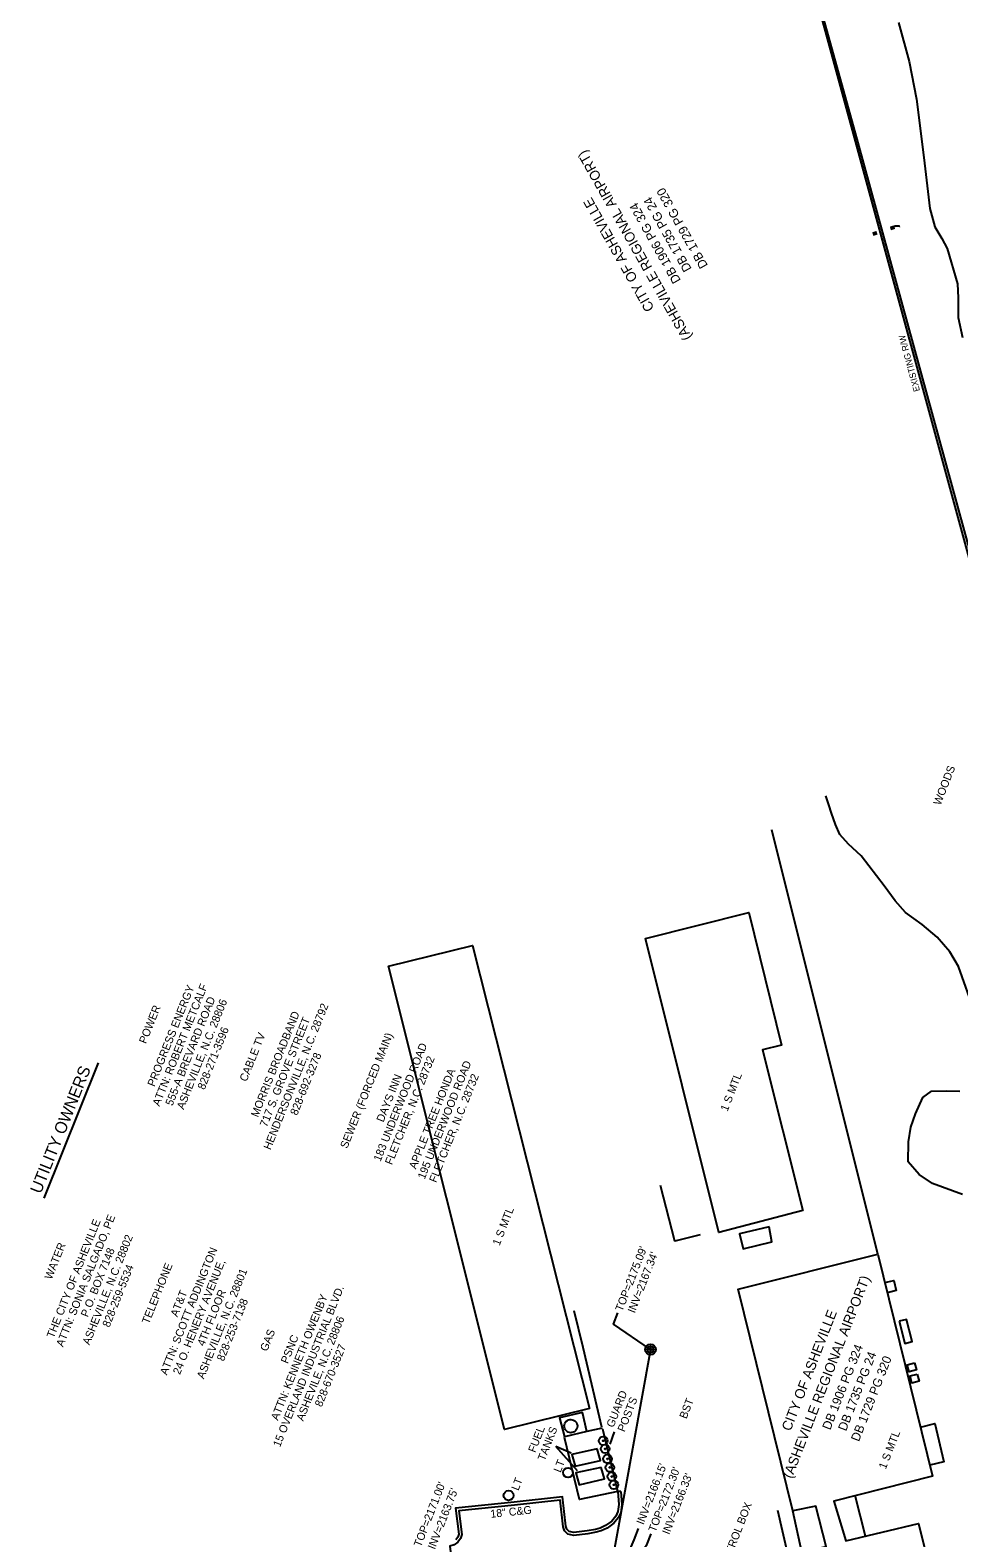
# Model space of a CAD drawing. Extents: x 945964 to 948456, y 631061 to 636061.
# Drawn here: x 946196 to 946664, y 633631 to 634391 of the extents above; entities that cross this region are included whole.
import ezdxf

# ---------------------------------------------------------------- set-up
doc = ezdxf.new("R2010")
doc.units = 0
for name, color, linetype in [('Exist Building', 7, 'Continuous'), ('Exist Building Text', 7, 'Continuous'), ('Exist Horizontal Alignment', 7, 'Continuous'), ('Exist Other Culture AG Tank', 7, 'Continuous'), ('Exist Other Culture AG Tank Leader', 7, 'Continuous'), ('Exist Other Culture AG Tank Text', 7, 'Continuous'), ('Exist Other Culture Fence Line', 7, 'Continuous'), ('Exist Other Culture Located Object CELL', 7, 'Continuous'), ('Exist Other Culture Located Object Leader', 7, 'Continuous'), ('Exist Other Culture Located Object Text', 7, 'Continuous'), ('Exist Property Deed Book Text', 7, 'Continuous'), ('Exist Property Owner Text', 7, 'Continuous'), ('Exist Right of Way Control of Access CA Symbol CELL', 7, 'Continuous'), ('Exist Right of Way Line', 7, 'Continuous'), ('Exist Right of Way Line Text', 7, 'Continuous'), ('Exist Roads Curbs', 7, 'Continuous'), ('Exist Roads Curbs Text', 7, 'Continuous'), ('Exist Roads EOP', 7, 'Continuous'), ('Exist Roads EOP Other', 7, 'Continuous'), ('Exist Roads EOP Other Text', 7, 'Continuous'), ('Exist Structure Minor Catch Basin Top Elevation', 7, 'Continuous'), ('Exist Structure Minor Pipes HDPE 15 Inch Invert', 7, 'Continuous'), ('Exist Structure Minor Pipes HDPE 18 Inch Invert', 7, 'Continuous'), ('Exist Utilities Gas UG Line Text', 7, 'Continuous'), ('Exist Utilities Other Pole CELL', 7, 'Continuous'), ('Exist Utilities Other Pole Text', 7, 'Continuous'), ('Exist Utilities Power UG Cable Text', 7, 'Continuous'), ('Exist Utilities Sanitary Sewer Manhole CELL', 7, 'Continuous'), ('Exist Utilities Sanitary Sewer Manhole Top Elevation', 7, 'Continuous'), ('Exist Utilities Sanitary Sewer UG Line', 7, 'Continuous'), ('Exist Utilities Sanitary Sewer UG Line Invert Elevation', 7, 'Continuous'), ('Exist Utilities Sanitary Sewer UG Line Text', 7, 'Continuous'), ('Exist Utilities Telephone UG Cable Text', 7, 'Continuous'), ('Exist Utilities TV UG Cable Text', 7, 'Continuous'), ('Exist Utilities Water UG Line', 7, 'Continuous'), ('Exist Utilities Water UG Line Text', 7, 'Continuous'), ('Exist Vegetation Woods Line', 7, 'Continuous'), ('Exist Vegetation Woods Line Text', 7, 'Continuous')]:
    doc.layers.add(name, color=color, linetype=linetype)

# ---------------------------------------------------------------- blocks, each defined once
blk = doc.blocks.new('EXIST UTILITIES SANITARY SEWER MANHOLE')
at = {"layer": 'Exist Utilities Sanitary Sewer Manhole CELL'}
blk.add_lwpolyline([(0, 0.034), (0, -0.034), (0, 0), (0.034, 0), (-0.034, 0)], dxfattribs=at)
for radius in [0.0539, 0.0342]:
    blk.add_circle((0, 0), radius, dxfattribs=at)
blk = doc.blocks.new('EXIST UTILITIES OTHER POLE')
at = {"layer": 'Exist Utilities Other Pole CELL'}
blk.add_circle((0, 0), 0.0493, dxfattribs=at)
blk = doc.blocks.new('EXIST OTHER CULTURE LOCATED OBJECT')
at = {"layer": 'Exist Other Culture Located Object CELL'}
for radius in [0.0436, 0.0048]:
    blk.add_circle((0, 0), radius, dxfattribs=at)

msp = doc.modelspace()

# ---------------------------------------------------------------- linework, layer by layer
at = {"layer": 'Exist Building'}
for points in [[(946585.51, 633796), (946543.09, 633784.88), (946506.06, 633933.07), (946558.17, 633946.19), (946574.77, 633879.35), (946565.18, 633877.05)], [(946477.89, 633696.25), (946435.09, 633685.56), (946376.62, 633919.21), (946418.84, 633929.55)], [(946568.47, 633787.79), (946553.56, 633784.29), (946555.39, 633776.67), (946569.81, 633780.2)], [(946623.36, 633773.95), (946650.9, 633662.1), (946601.09, 633649.58), (946607.19, 633629.53), (946643.78, 633638.28), (946658.46, 633579.54), (946600.11, 633564.89), (946592.6, 633586.8), (946584.76, 633584.87), (946581, 633599.34), (946588.81, 633601.19), (946585.03, 633623.78), (946597.19, 633626.71), (946592.09, 633646.95), (946580.49, 633644.56), (946552.84, 633756.37)]]:
    msp.add_lwpolyline(points, close=True, dxfattribs=at)
for points in [[(946476.56, 633684.58), (946474.3, 633694.22), (946462.85, 633691.49), (946465.22, 633681.98)], [(946484.35, 633686.25), (946476.56, 633684.58), (946465.22, 633681.98)]]:
    msp.add_lwpolyline(points, dxfattribs=at)
at = {"layer": 'Exist Horizontal Alignment'}
msp.add_arc((941215.95, 632723.7), 5729.58, 16.26287, 23.58343, dxfattribs=at)
at = {"layer": 'Exist Other Culture AG Tank'}
for points in [[(946481.69, 633675.79), (946469.02, 633673.09), (946470.62, 633667.11), (946483.37, 633670.02), (946481.78, 633675.83)], [(946483.73, 633666.48), (946471.07, 633663.78), (946472.67, 633657.8), (946485.42, 633660.71), (946483.83, 633666.52)]]:
    msp.add_lwpolyline(points, dxfattribs=at)
msp.add_ellipse((946468.49, 633687.32), major_axis=(3.04, -1.35), ratio=0.999999, dxfattribs=at)
at = {"layer": 'Exist Other Culture AG Tank Leader'}
for points in [[(946468.58, 633673.73), (946460.88, 633676.99)], [(946471.9, 633664.71), (946460.88, 633676.99)]]:
    msp.add_lwpolyline(points, dxfattribs=at)
at = {"layer": 'Exist Other Culture Fence Line'}
for points in [[(946878.27, 633607.67), (946888.64, 633643.47), (946880.77, 633649.9), (946866.85, 633668.33), (946820.19, 633740.22), (946774.6, 633810.54), (946747.06, 633866.82), (946715.89, 633963.4), (946695.94, 634031.44), (946673.26, 634115.84), (946613.35, 634334.02), (946562.75, 634516.44)], [(946623.36, 633773.95), (946569.82, 633987.91)]]:
    msp.add_lwpolyline(points, dxfattribs=at)
at = {"layer": 'Exist Other Culture Located Object Leader'}
msp.add_lwpolyline([(946488.38, 633678.18), (946490.47, 633684.46)], dxfattribs=at)
at = {"layer": 'Exist Right of Way Control of Access CA Symbol CELL'}
msp.add_line((946623.16, 634293.78), (946623.16, 634293.78), dxfattribs=at)
at = {"layer": 'Exist Right of Way Line'}
msp.add_lwpolyline([(946574.77, 634471.14), (946704.36, 633996.2)], dxfattribs=at)
at = {"layer": 'Exist Roads Curbs'}
for points in [[(946492.19, 633654.29), (946492.71, 633647.87), (946492.23, 633644.24), (946491.13, 633641.88), (946489.13, 633639.47), (946486.01, 633637.17), (946483.34, 633635.89), (946480.96, 633635.29), (946476.78, 633634.55), (946470.03, 633633.77), (946467.67, 633634.19), (946466.54, 633635.33), (946466.01, 633636.85), (946464.35, 633651.62), (946439.85, 633648.99), (946410.38, 633645.9), (946411.95, 633632.87), (946411.54, 633631.3), (946410.44, 633629.95)], [(946578.16, 633622.11), (946572.81, 633644.83)]]:
    msp.add_lwpolyline(points, dxfattribs=at)
at = {"layer": 'Exist Roads EOP'}
msp.add_lwpolyline([(946493.69, 633654.41), (946494.22, 633647.83), (946493.68, 633643.82), (946492.41, 633641.07), (946490.17, 633638.37), (946486.79, 633635.88), (946483.85, 633634.47), (946481.28, 633633.83), (946477, 633633.06), (946469.98, 633632.26), (946466.94, 633632.79), (946465.23, 633634.52), (946464.54, 633636.52), (946463.03, 633649.97), (946440.01, 633647.49), (946412.05, 633644.57), (946413.47, 633632.77), (946412.92, 633630.61), (946411.47, 633628.83), (946409.61, 633627.56), (946407.41, 633626.84), (946409.13, 633613.1)], dxfattribs=at)
at = {"layer": 'Exist Roads EOP Other'}
for points in [[(946533.63, 633783.73), (946520.93, 633780.46), (946513.67, 633808.64)], [(946626.85, 633759.77), (946631.43, 633760.78), (946632.57, 633755.64), (946628.13, 633754.55)], [(946484.16, 633686.71), (946474.64, 633726.97), (946470.13, 633745.43)], [(946493.69, 633654.41), (946492.69, 633654.33), (946492.19, 633654.29), (946484.57, 633685.73)], [(946644.81, 633686.81), (946652.11, 633688.58), (946656.56, 633669.32), (946649.52, 633667.71)], [(946492.19, 633654.29), (946472.83, 633650.29), (946465.3, 633681.56)], [(946617.11, 633631.9), (946611.8, 633652.27)], [(946585.03, 633623.78), (946580.49, 633644.56)]]:
    msp.add_lwpolyline(points, dxfattribs=at)
for points in [[(946634, 633740.18), (946636.88, 633729.01), (946640.56, 633729.96), (946637.67, 633741.13)], [(946641.77, 633719.22), (946642.78, 633715.63), (946639.15, 633714.6), (946638.13, 633718.2)], [(946643.18, 633713.58), (946644.11, 633709.98), (946640.48, 633709.03), (946639.54, 633712.63)]]:
    msp.add_lwpolyline(points, close=True, dxfattribs=at)
at = {"layer": 'Exist Structure Minor Catch Basin Top Elevation'}
msp.add_lwpolyline([(946493.66, 633612.2), (946506.75, 633627.44), (946508.94, 633633.03)], dxfattribs=at)
at = {"layer": 'Exist Structure Minor Pipes HDPE 18 Inch Invert'}
msp.add_lwpolyline([(946492.54, 633611.54), (946500.47, 633630.05), (946502.66, 633635.64)], dxfattribs=at)
at = {"layer": 'Exist Utilities Sanitary Sewer Manhole Top Elevation'}
msp.add_lwpolyline([(946508.67, 633725.95), (946490.07, 633738.77), (946492.26, 633744.36)], dxfattribs=at)
at = {"layer": 'Exist Utilities Sanitary Sewer UG Line'}
msp.add_lwpolyline([(946508.67, 633725.95), (946453.33, 633420.85)], dxfattribs=at)
at = {"layer": 'Exist Utilities Water UG Line'}
msp.add_lwpolyline([(946202.9, 633802.22), (946230.27, 633870.48)], dxfattribs=at)
at = {"layer": 'Exist Vegetation Woods Line'}
for points in [[(946633.79, 634394.82), (946639.02, 634375.12), (946642.78, 634356.07), (946646.5, 634326.78), (946649.44, 634301.05), (946652.06, 634291.81), (946655.53, 634285.87), (946658.26, 634280.77), (946663.5, 634263.07), (946663.77, 634255.98), (946663.76, 634246.02), (946665.97, 634236)], [(946672.25, 633895.82), (946663.91, 633919.02), (946659.68, 633926.33), (946653.15, 633933.83), (946645.66, 633940.2), (946637.22, 633946.1), (946632.1, 633952.13), (946626.56, 633959.64), (946614.95, 633974.69), (946608.48, 633980.6), (946604.13, 633985.56), (946601.91, 633990.45), (946600, 633996.21), (946598.52, 634000.41), (946597.09, 634004.92)], [(946666.01, 633804.04), (946650.93, 633809.55), (946644.19, 633814.08), (946638.52, 633820.44), (946638.83, 633830.55), (946639.89, 633837.99), (946642.22, 633844.78), (946645.95, 633852.97), (946650.31, 633856.2), (946658.1, 633856.38), (946664.72, 633856.09)]]:
    msp.add_lwpolyline(points, dxfattribs=at)

# ---------------------------------------------------------------- block references
at = {"layer": 'Exist Other Culture Located Object CELL', "xscale": 50, "yscale": 50}
for p in [(946484.86, 633679.92), (946485.8, 633675.85), (946487.02, 633670.77), (946488.1, 633666.51), (946489.19, 633661.9), (946490.24, 633657.72)]:
    msp.add_blockref('EXIST OTHER CULTURE LOCATED OBJECT', p, dxfattribs=at)
at = {"layer": 'Exist Utilities Other Pole CELL', "xscale": 50, "yscale": 50}
for p in [(946467.1, 633663.91), (946437.08, 633652.37)]:
    msp.add_blockref('EXIST UTILITIES OTHER POLE', p, dxfattribs=at)
at = {"layer": 'Exist Utilities Sanitary Sewer Manhole CELL', "xscale": 50, "yscale": 50}
msp.add_blockref('EXIST UTILITIES SANITARY SEWER MANHOLE', (946508.67, 633725.95), dxfattribs=at)

# ---------------------------------------------------------------- texts
at = {"layer": 'Exist Building Text'}
for s, p in [('1 S MTL', (946547.49, 633845.62)), ('1 S MTL', (946432.53, 633777.96)), ('1 S MTL', (946627.28, 633665.31)), ('GATE CONTROL BOX', (946539.86, 633596.76))]:
    msp.add_text(s, height=4, rotation=68.61896, dxfattribs=at).set_placement(p)
at = {"layer": 'Exist Other Culture AG Tank Text'}
for s, p in [('FUEL', (946450.53, 633673.66)), ('TANKS', (946455.32, 633669.45))]:
    msp.add_text(s, height=4, rotation=68.61896, dxfattribs=at).set_placement(p)
at = {"layer": 'Exist Other Culture Located Object Text'}
for s, p in [('GUARD', (946489.99, 633686.29)), ('POSTS', (946495.57, 633684.09))]:
    msp.add_text(s, height=4, rotation=68.61896, dxfattribs=at).set_placement(p)
at = {"layer": 'Exist Property Deed Book Text'}
for s, rotation, p in [('DB 1729 PG 320', 119.40565, (946537.72, 634272.29)), ('DB 1906 PG 324', 119.40565, (946524.07, 634264.76)), ('DB 1735 PG 24', 119.40565, (946529.54, 634270.6)), ('DB 1906 PG 324', 68.53343, (946599.28, 633685.05)), ('DB 1735 PG 24', 68.53343, (946607.26, 633684.49)), ('DB 1729 PG 320', 68.53343, (946613.73, 633679.21))]:
    msp.add_text(s, height=4.5, rotation=rotation, dxfattribs=at).set_placement(p)
at = {"layer": 'Exist Property Owner Text'}
for s, rotation, p in [('(ASHEVILLE REGIONAL AIRPORT)', 119.53837, (946529.66, 634236.17)), ('CITY OF ASHEVILLE', 119.53837, (946510.73, 634250.72)), ('(ASHEVILLE REGIONAL AIRPORT)', 68.66615, (946579.92, 633660.58)), ('CITY OF ASHEVILLE', 68.66615, (946579.26, 633684.45))]:
    msp.add_text(s, height=5, rotation=rotation, dxfattribs=at).set_placement(p)
at = {"layer": 'Exist Right of Way Control of Access CA Symbol CELL'}
msp.add_text(';', height=15, rotation=107.63565, dxfattribs=at).set_placement((946632.58, 634288.91))
at = {"layer": 'Exist Right of Way Line Text'}
msp.add_text('EXISTING R/W', height=3.2, rotation=105.26129, dxfattribs=at).set_placement((946644.59, 634209.18))
at = {"layer": 'Exist Roads Curbs Text'}
msp.add_text('18" C&G', height=4, rotation=5.97571, dxfattribs=at).set_placement((946428.13, 633641.07))
at = {"layer": 'Exist Roads EOP Other Text'}
msp.add_text('BST', height=4, rotation=68.93497, dxfattribs=at).set_placement((946526.79, 633690.68))
at = {"layer": 'Exist Structure Minor Catch Basin Top Elevation'}
for s, p in [("TOP=2172.30'", (946511.16, 633633.58)), ("TOP=2171.00'", (946392.85, 633626.1))]:
    msp.add_text(s, height=4, rotation=68.6189, dxfattribs=at).set_placement(p)
at = {"layer": 'Exist Structure Minor Pipes HDPE 15 Inch Invert'}
msp.add_text("INV=2166.33'", height=4, rotation=68.6189, dxfattribs=at).set_placement((946518.08, 633632.38))
at = {"layer": 'Exist Structure Minor Pipes HDPE 18 Inch Invert'}
for s, p in [("INV=2166.15'", (946505.14, 633637.32)), ("INV=2163.75'", (946399.91, 633624.88))]:
    msp.add_text(s, height=4, rotation=68.6189, dxfattribs=at).set_placement(p)
at = {"layer": 'Exist Utilities Gas UG Line Text'}
for s, p in [('ATTN: KENNETH OWENBY', (946320.76, 633689.88)), ('15 OVERLAND INDUSTRIAL BLVD.', (946321.84, 633676.45)), ('ASHEVILE, N.C. 28806', (946333.56, 633689.57)), ('GAS', (946315.31, 633724.67)), ('PSNC', (946325.77, 633718.51)), ('828-670-3527', (946342.87, 633696.66))]:
    msp.add_text(s, height=4, rotation=68.15232, dxfattribs=at).set_placement(p)
at = {"layer": 'Exist Utilities Other Pole Text'}
for p in [(946463.31, 633663.62), (946442.02, 633654.53)]:
    msp.add_text('LT', height=4, rotation=68.61896, dxfattribs=at).set_placement(p)
at = {"layer": 'Exist Utilities Power UG Cable Text'}
for s, p in [('PROGRESS ENERGY', (946258.51, 633858.1)), ('ATTN: ROBERT METCALF', (946261.03, 633848.27)), ('POWER', (946254.25, 633879.73)), ('555-A BREVARD ROAD', (946267.56, 633848.43)), ('ASHEVILLE, N.C. 28806', (946273.29, 633846.61)), ('828-271-3596', (946283.75, 633856.56))]:
    msp.add_text(s, height=4, rotation=68.15232, dxfattribs=at).set_placement(p)
at = {"layer": 'Exist Utilities Sanitary Sewer Manhole Top Elevation'}
msp.add_text("TOP=2175.09'", height=4, rotation=68.6189, dxfattribs=at).set_placement((946494.46, 633744.8))
at = {"layer": 'Exist Utilities Sanitary Sewer UG Line Invert Elevation'}
msp.add_text("INV=2167.34'", height=4, rotation=68.6189, dxfattribs=at).set_placement((946500.73, 633743.97))
at = {"layer": 'Exist Utilities Sanitary Sewer UG Line Text'}
for s, p in [('SEWER (FORCED MAIN)', (946355.72, 633826.93)), ('183 UNDERWOOD ROAD', (946372.49, 633820.37)), ('FLETCHER, N.C. 28732', (946378.28, 633818.7)), ('195 UNDERWOOD ROAD', (946394.77, 633811.44)), ('DAYS INN', (946373.98, 633840.2)), ('APPLE TREE HONDA', (946390.36, 633816.57)), ('FLETCHER, N.C. 28732', (946400.56, 633809.76))]:
    msp.add_text(s, height=4, rotation=68.15232, dxfattribs=at).set_placement(p)
at = {"layer": 'Exist Utilities Telephone UG Cable Text'}
for s, p in [('ATTN: SCOTT ADDINGTON', (946264.79, 633712.71)), ('TELEPHONE', (946255.72, 633738.46)), ('24 O. HENERY AVENUE,', (946271.36, 633712.97)), ('ASHEVILLE, N.C. 28801', (946283.42, 633710.81)), ('AT&T', (946270.1, 633742.08)), ('4TH FLOOR', (946283.57, 633727.31)), ('828-253-7138', (946293.46, 633719.71))]:
    msp.add_text(s, height=4, rotation=68.15232, dxfattribs=at).set_placement(p)
at = {"layer": 'Exist Utilities TV UG Cable Text'}
for s, p in [('HENDERSONVILLE, N.C. 28792', (946317.04, 633826.26)), ('MORRIS BROADBAND', (946310.7, 633842.72)), ('717 S. GROVE STREET', (946315.18, 633837.76)), ('CABLE TV', (946304.96, 633860.63)), ('828-692-3278', (946330.46, 633843.62))]:
    msp.add_text(s, height=4, rotation=68.15232, dxfattribs=at).set_placement(p)
at = {"layer": 'Exist Utilities Water UG Line Text'}
for s, height, p in [('UTILITY OWNERS', 6, (946201.17, 633804.04)), ('THE CITY OF ASHEVILLE', 4, (946207.72, 633731.34)), ('ATTN: SONIA SALGADO, PE', 4, (946212.44, 633726.97)), ('ASHEVILLE, N.C. 28802', 4, (946225.74, 633727.9)), ('WATER', 4, (946206.64, 633760.87)), ('P.O. BOX 7148', 4, (946224.9, 633741.94)), ('828-259-5534', 4, (946235.77, 633736.81))]:
    msp.add_text(s, height=height, rotation=68.15232, dxfattribs=at).set_placement(p)
at = {"layer": 'Exist Vegetation Woods Line Text'}
msp.add_text('WOODS', height=4, rotation=68.61896, dxfattribs=at).set_placement((946654.86, 633999.9))

doc.saveas('drawing.dxf')
